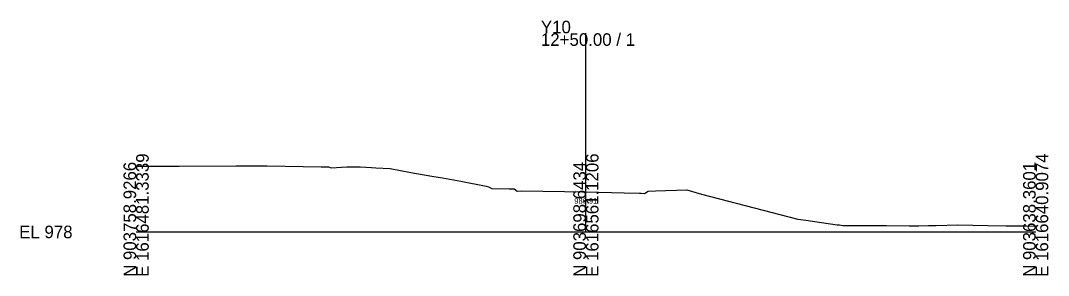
# Model space of a CAD drawing. Extents: x -26 to 203, y -10 to 3046.
# Drawn here: x -25.7 to 202.8, y 2490.3 to 2547.1 of the extents above; entities that cross this region are included whole.
import ezdxf

# ---------------------------------------------------------------- set-up
doc = ezdxf.new("R2010")
doc.units = 0
for name, color, linetype in [('Exist Cross Section Cell', 7, 'Continuous'), ('Exist XS Center Line Elevation Label', 7, 'Continuous'), ('Exist XS Ground Line', 7, 'Continuous')]:
    doc.layers.add(name, color=color, linetype=linetype)

msp = doc.modelspace()

# ---------------------------------------------------------------- linework, layer by layer
at = {"layer": 'Exist Cross Section Cell'}
for p, q in [((100, 2500), (100, 2544.24)), ((0, 2500), (100, 2500)), ((100, 2500), (200, 2500))]:
    msp.add_line(p, q, dxfattribs=at)
at = {"layer": 'Exist XS Ground Line'}
for p, q in [((0, 2514.64), (1.49, 2514.63)), ((1.49, 2514.63), (9.57, 2514.63)), ((9.57, 2514.63), (22.19, 2514.71)), ((22.19, 2514.71), (29.13, 2514.75)), ((29.13, 2514.75), (41.17, 2514.5)), ((41.17, 2514.5), (42.78, 2514.5)), ((42.78, 2514.5), (43.35, 2514.31)), ((43.35, 2514.31), (46.88, 2514.48)), ((46.88, 2514.48), (49.19, 2514.52)), ((49.19, 2514.52), (49.79, 2514.47)), ((49.79, 2514.47), (52.31, 2514.33)), ((52.31, 2514.33), (53.27, 2514.29)), ((53.27, 2514.29), (56.45, 2514.1)), ((56.45, 2514.1), (61.11, 2513.23)), ((61.11, 2513.23), (65.78, 2512.45)), ((65.78, 2512.45), (68.15, 2512.03)), ((68.15, 2512.03), (72.17, 2511.3)), ((72.17, 2511.3), (77.86, 2510.21)), ((77.86, 2510.21), (78.32, 2510.03)), ((78.32, 2510.03), (79.11, 2509.69)), ((79.11, 2509.69), (82.91, 2509.61)), ((82.91, 2509.61), (84.03, 2509.58)), ((84.03, 2509.58), (84.74, 2509.11)), ((115.49, 2509.15), (122.45, 2509.38)), ((122.45, 2509.38), (125.7, 2508.42)), ((84.74, 2509.11), (85.58, 2509.14)), ((85.58, 2509.14), (95.26, 2509)), ((95.26, 2509), (99.14, 2508.92)), ((99.14, 2508.92), (100, 2508.91)), ((100, 2508.91), (108.54, 2508.72)), ((108.54, 2508.72), (111.89, 2508.65)), ((111.89, 2508.65), (112.3, 2508.63)), ((112.3, 2508.63), (113, 2508.59)), ((113, 2508.59), (113.82, 2509.07)), ((113.82, 2509.07), (115.49, 2509.15)), ((125.7, 2508.42), (147.15, 2502.87)), ((147.15, 2502.87), (148.92, 2502.61)), ((148.92, 2502.61), (155.9, 2501.6)), ((155.9, 2501.6), (156.39, 2501.55)), ((156.39, 2501.55), (157.11, 2501.47)), ((157.11, 2501.47), (161.94, 2501.45)), ((161.94, 2501.45), (166.81, 2501.4)), ((166.81, 2501.4), (171.9, 2501.37)), ((171.9, 2501.37), (174.06, 2501.37)), ((174.06, 2501.37), (176.2, 2501.47)), ((176.2, 2501.47), (177.86, 2501.45)), ((177.86, 2501.45), (182.69, 2501.55)), ((182.69, 2501.55), (189.34, 2501.47)), ((189.34, 2501.47), (193.39, 2501.37)), ((193.39, 2501.37), (195.63, 2501.38)), ((195.63, 2501.38), (197.99, 2501.35)), ((197.99, 2501.35), (200, 2501.27))]:
    msp.add_line(p, q, dxfattribs=at)

# ---------------------------------------------------------------- texts
at = {"layer": 'Exist Cross Section Cell'}
for s, p in [('Y10', (90, 2544.24)), ('12+50.00 / 1', (90, 2541.44)), ('EL 978', (-26, 2498.6))]:
    msp.add_text(s, height=2.8, dxfattribs=at).set_placement(p)
for s, p in [('E 1616481.3339', (2.8, 2490)), ('E 1616561.1206', (102.8, 2490)), ('E 1616640.9074', (202.8, 2490)), ('N 903758.9266', (0, 2490)), ('N 903698.6434', (100, 2490)), ('N 903638.3601', (200, 2490))]:
    msp.add_text(s, height=2.8, rotation=90, dxfattribs=at).set_placement(p)
at = {"layer": 'Exist XS Center Line Elevation Label'}
msp.add_text('986.91', height=1.25, dxfattribs=at).set_placement((97.42, 2506.28))

doc.saveas('drawing.dxf')
